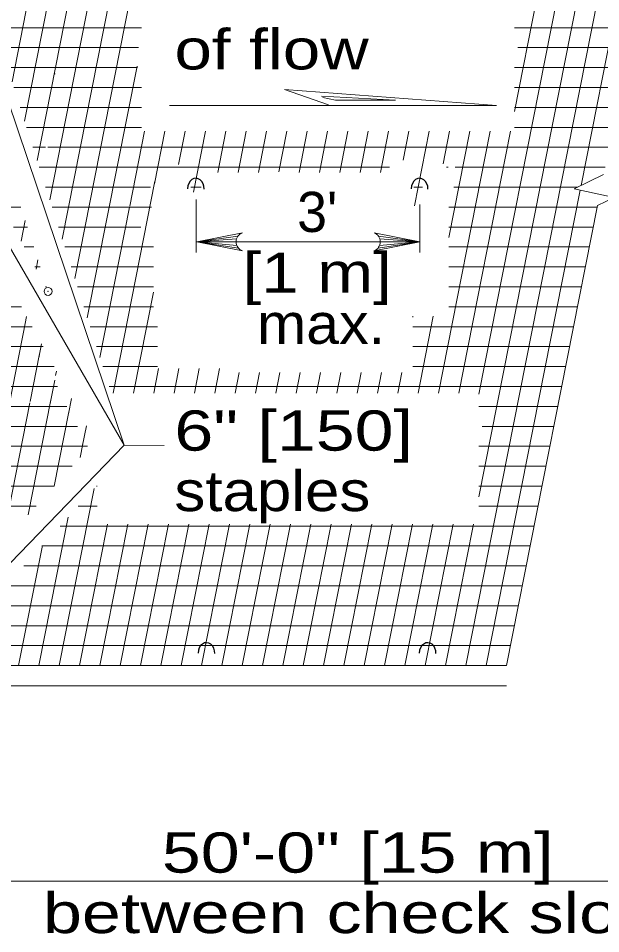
# Model space of a CAD drawing. Extents: x 1083.1 to 1117.1, y 719.4 to 741.4.
# Drawn here: x 1101.052 to 1103.312, y 726.357 to 729.91 of the extents above; entities that cross this region are included whole.
import ezdxf
from ezdxf.enums import TextEntityAlignment as Align

# ---------------------------------------------------------------- set-up
doc = ezdxf.new("R2010")
doc.units = 0
doc.header["$LTSCALE"] = 0.062
doc.header["$PDMODE"] = 32
doc.header["$PDSIZE"] = 0.031
doc.layers.add('1', color=7, linetype='Continuous', lineweight=13)

msp = doc.modelspace()

# ---------------------------------------------------------------- linework, layer by layer
at = {"layer": '1'}
for p, q in [((1101.07625, 729.5115), (1101.36217, 730.95708)), ((1102.78825, 727.39792), (1103.49175, 730.95708)), ((1102.83858, 728.45092), (1103.334, 730.95708)), ((1102.83867, 728.05233), (1103.41283, 730.95708)), ((1102.97675, 729.54875), (1103.25508, 730.95708)), ((1103.23542, 729.26133), (1103.57058, 730.95708)), ((1101.17367, 729.2055), (1101.48558, 730.7835)), ((1101.46192, 728.25383), (1100.61817, 730.75558)), ((1101.22225, 729.05292), (1101.53617, 730.64)), ((1101.12475, 729.35892), (1101.3035, 730.26167)), ((1101.02758, 729.66417), (1101.11492, 730.10608)), ((1101.27092, 728.9), (1101.50892, 730.10408)), ((1101.19833, 729.87383), (1100.96083, 729.87383)), ((1101.52983, 729.87383), (1101.19833, 729.87383)), ((1103.43542, 729.87383), (1102.97675, 729.87383)), ((1101.18775, 729.7965), (1100.9855, 729.7965)), ((1101.51842, 729.7965), (1101.18775, 729.7965)), ((1103.42008, 729.7965), (1102.98983, 729.7965)), ((1101.17717, 729.71908), (1101.01008, 729.71908)), ((1101.51475, 729.71908), (1101.17717, 729.71908)), ((1101.31958, 728.74725), (1101.51275, 729.72433)), ((1103.40483, 729.71908), (1102.97675, 729.71908)), ((1101.19017, 729.695), (1101.195, 729.695)), ((1101.16875, 729.64175), (1101.03475, 729.64175)), ((1101.52983, 729.64175), (1101.16875, 729.64175)), ((1103.3895, 729.64175), (1102.97675, 729.64175)), ((1101.17075, 729.56442), (1101.05942, 729.56442)), ((1101.52983, 729.56442), (1101.17075, 729.56442)), ((1101.63817, 729.57175), (1102.90775, 729.57175)), ((1103.37417, 729.56442), (1102.97675, 729.56442)), ((1101.18008, 729.487), (1101.084, 729.487)), ((1101.52983, 729.487), (1101.18008, 729.487)), ((1103.359, 729.487), (1102.97675, 729.487)), ((1101.48417, 729.18058), (1101.54192, 729.47283)), ((1101.58033, 729.26833), (1101.62075, 729.47283)), ((1101.674, 729.34317), (1101.69967, 729.47283)), ((1101.73183, 729.23608), (1101.77858, 729.47283)), ((1101.8255, 729.3115), (1101.85742, 729.47283)), ((1101.90442, 729.3115), (1101.93633, 729.47283)), ((1101.98325, 729.3115), (1102.01517, 729.47283)), ((1102.06283, 729.31483), (1102.09408, 729.47283)), ((1102.141, 729.3115), (1102.17292, 729.47283)), ((1102.21992, 729.3115), (1102.25183, 729.47283)), ((1102.29883, 729.3115), (1102.33058, 729.47242)), ((1102.37767, 729.3115), (1102.40958, 729.47283)), ((1102.45658, 729.3115), (1102.48842, 729.47283)), ((1102.54483, 729.35925), (1102.56733, 729.47283)), ((1102.58858, 729.18175), (1102.64617, 729.47283)), ((1102.68167, 728.45517), (1102.88283, 729.47283)), ((1102.69983, 729.34525), (1102.72508, 729.47283)), ((1102.72208, 729.05917), (1102.80392, 729.47283)), ((1102.7605, 728.45517), (1102.96175, 729.47283)), ((1101.15683, 729.40967), (1101.10867, 729.40967)), ((1101.16033, 729.33225), (1101.13325, 729.33225)), ((1101.86742, 729.33225), (1101.80475, 729.33225)), ((1102.71367, 729.33225), (1102.72017, 729.33225)), ((1102.74633, 729.33225), (1103.32833, 729.33225)), ((1101.41958, 728.45517), (1101.58217, 729.27775)), ((1103.32267, 729.30358), (1103.20867, 729.24833)), ((1101.1615, 729.25492), (1101.15792, 729.25492)), ((1101.75983, 729.25492), (1101.72083, 729.25492)), ((1101.72083, 729.25492), (1101.76192, 729.25492)), ((1102.586, 729.25492), (1102.62025, 729.25492)), ((1102.74142, 729.25492), (1103.22225, 729.25492)), ((1102.86708, 727.39792), (1103.23183, 729.24325)), ((1101.74133, 729.20692), (1101.74133, 729.00108)), ((1101.062, 729.1775), (1100.99092, 729.1775)), ((1101.36825, 728.59433), (1101.4835, 729.177)), ((1102.60925, 729.18758), (1102.60925, 729.00108)), ((1102.72208, 729.1775), (1103.29775, 729.1775)), ((1102.946, 727.39792), (1103.29883, 729.18333)), ((1101.03267, 729.10017), (1101.08692, 729.10017)), ((1101.06258, 729.04467), (1101.07867, 729.12583)), ((1101.20717, 729.10017), (1101.52725, 729.10017)), ((1102.72208, 729.10017), (1103.2825, 729.10017)), ((1101.90442, 729.06517), (1101.74417, 729.04275)), ((1102.44908, 729.06517), (1102.60933, 729.04275)), ((1102.72208, 729.06808), (1102.72217, 729.0685)), ((1101.74133, 729.04275), (1102.60933, 729.04275)), ((1101.899, 729.05408), (1101.74417, 729.04275)), ((1101.89733, 729.04275), (1101.74417, 729.04275)), ((1101.90017, 729.02833), (1101.74417, 729.04275)), ((1101.90633, 729.018), (1101.74417, 729.04275)), ((1102.44717, 729.018), (1102.60933, 729.04275)), ((1102.45333, 729.02833), (1102.60933, 729.04275)), ((1102.4545, 729.05408), (1102.60933, 729.04275)), ((1102.45617, 729.04275), (1102.60933, 729.04275)), ((1101.07433, 729.02275), (1101.11183, 729.02275)), ((1101.23183, 729.02275), (1101.31108, 729.02275)), ((1101.31175, 729.02275), (1101.57592, 729.02275)), ((1102.72208, 729.02275), (1103.26717, 729.02275)), ((1101.12058, 728.93708), (1101.12775, 728.97333)), ((1101.11608, 728.94542), (1101.13675, 728.94542)), ((1101.2565, 728.94542), (1101.57592, 728.94542)), ((1102.72208, 728.94542), (1103.25183, 728.94542)), ((1101.15783, 728.868), (1101.16167, 728.868)), ((1101.28108, 728.868), (1101.28533, 728.868)), ((1101.28533, 728.868), (1101.57592, 728.868)), ((1102.72208, 728.868), (1103.23658, 728.868)), ((1101.4985, 728.45517), (1101.57592, 728.84675)), ((1100.64575, 728.79067), (1101.05875, 728.79067)), ((1101.0585, 728.79067), (1101.06367, 728.79067)), ((1101.30575, 728.79067), (1101.57592, 728.79067)), ((1102.72208, 728.79067), (1103.22125, 728.79067)), ((1101.07883, 728.72617), (1101.08417, 728.75308)), ((1102.58242, 728.75092), (1102.58308, 728.75425)), ((1102.60275, 728.45517), (1102.66183, 728.75425)), ((1100.6305, 728.71325), (1101.10592, 728.71325)), ((1101.016, 728.4085), (1101.08125, 728.73875)), ((1101.33125, 728.71325), (1101.59175, 728.71325)), ((1102.58242, 728.71325), (1103.206, 728.71325)), ((1100.61517, 728.63592), (1101.14817, 728.63592)), ((1101.13125, 728.593), (1101.142, 728.64717)), ((1101.355, 728.63592), (1101.42058, 728.63592)), ((1101.355, 728.63592), (1101.59175, 728.63592)), ((1102.58242, 728.63592), (1103.19067, 728.63592)), ((1101.09775, 728.42333), (1101.13417, 728.6075)), ((1100.59983, 728.5585), (1101.1565, 728.5585)), ((1101.05475, 728.5585), (1101.19033, 728.5585)), ((1101.19658, 728.52367), (1101.2, 728.54092)), ((1101.37967, 728.5585), (1101.59175, 728.5585)), ((1101.5775, 728.45517), (1101.59633, 728.5505)), ((1101.65625, 728.45517), (1101.67508, 728.5505)), ((1101.73517, 728.45517), (1101.754, 728.5505)), ((1101.814, 728.45517), (1101.83283, 728.5505)), ((1101.89292, 728.45517), (1101.90883, 728.536)), ((1101.97175, 728.45517), (1101.98775, 728.536)), ((1102.05075, 728.45517), (1102.06667, 728.536)), ((1102.1295, 728.45517), (1102.1455, 728.536)), ((1102.20842, 728.45517), (1102.22442, 728.536)), ((1102.28733, 728.45517), (1102.30325, 728.536)), ((1102.36617, 728.45517), (1102.38217, 728.536)), ((1102.445, 728.45517), (1102.46092, 728.536)), ((1102.52392, 728.45517), (1102.53992, 728.536)), ((1102.58242, 728.5585), (1103.17542, 728.5585)), ((1101.17508, 728.41517), (1101.19292, 728.50542)), ((1100.58458, 728.48117), (1101.20433, 728.48117)), ((1101.40425, 728.48117), (1103.16017, 728.48117)), ((1101.08958, 727.98258), (1101.17783, 728.42908)), ((1101.246, 728.37508), (1101.25783, 728.43492)), ((1100.56925, 728.40383), (1101.23992, 728.40383)), ((1100.98858, 727.87075), (1101.09675, 728.41808)), ((1102.83858, 728.40383), (1103.14483, 728.40383)), ((1101.19058, 728.09442), (1101.2475, 728.3825)), ((1100.554, 728.32642), (1101.2815, 728.32642)), ((1101.2995, 728.24658), (1101.31575, 728.32883)), ((1102.85175, 728.32642), (1103.1295, 728.32642)), ((1100.96708, 728.24908), (1101.32, 728.24908)), ((1101.2915, 728.20625), (1101.30175, 728.25808)), ((1101.46192, 728.25383), (1101.61792, 728.25283)), ((1102.83858, 728.24908), (1103.11425, 728.24908)), ((1100.86633, 728.17167), (1101.26033, 728.17167)), ((1102.83867, 728.17167), (1103.09892, 728.17167)), ((1100.82008, 728.09433), (1101.19042, 728.09433)), ((1101.21067, 727.39792), (1101.34642, 728.08508)), ((1101.35483, 728.09433), (1101.35825, 728.09433)), ((1102.83867, 728.09433), (1103.08367, 728.09433)), ((1100.77883, 728.01692), (1101.12058, 728.01692)), ((1101.28425, 728.01692), (1101.35825, 728.01692)), ((1102.83867, 728.01692), (1103.06833, 728.01692)), ((1101.13175, 727.39792), (1101.24575, 727.97467)), ((1101.21375, 727.93958), (1103.053, 727.93958)), ((1101.2895, 727.39792), (1101.39792, 727.9465)), ((1101.36842, 727.39792), (1101.47683, 727.9465)), ((1101.44725, 727.39792), (1101.55575, 727.9465)), ((1101.52617, 727.39792), (1101.63458, 727.9465)), ((1101.605, 727.39792), (1101.7135, 727.9465)), ((1101.68392, 727.39792), (1101.79242, 727.9465)), ((1101.76283, 727.39792), (1101.87125, 727.9465)), ((1101.84167, 727.39792), (1101.95017, 727.9465)), ((1101.92058, 727.39792), (1102.029, 727.9465)), ((1101.99942, 727.39792), (1102.10783, 727.9465)), ((1102.07833, 727.39792), (1102.18675, 727.9465)), ((1102.15717, 727.39792), (1102.26567, 727.9465)), ((1102.23608, 727.39792), (1102.3445, 727.9465)), ((1102.31492, 727.39792), (1102.42342, 727.9465)), ((1102.39383, 727.39792), (1102.50225, 727.9465)), ((1102.47275, 727.39792), (1102.58117, 727.9465)), ((1102.55158, 727.39792), (1102.66, 727.9465)), ((1102.6305, 727.39792), (1102.73892, 727.9465)), ((1102.70933, 727.39792), (1102.81775, 727.9465)), ((1101.05292, 727.39792), (1101.14508, 727.86417)), ((1101.14325, 727.86217), (1103.03775, 727.86217)), ((1101.07275, 727.78483), (1103.02242, 727.78483)), ((1101.00225, 727.70742), (1103.00717, 727.70742)), ((1100.93167, 727.63008), (1102.99192, 727.63008)), ((1100.86117, 727.55267), (1102.97658, 727.55267)), ((1100.79067, 727.47533), (1102.96133, 727.47533)), ((1100.37042, 727.39792), (1102.946, 727.39792)), ((1100.37042, 727.31908), (1102.946, 727.31908)), ((1100.37042, 726.56167), (1101.59783, 726.56167)), ((1101.59783, 726.56167), (1103.66917, 726.56167))]:
    msp.add_line(p, q, dxfattribs=at)
for points in [[(1102.90775, 729.57175), (1102.08442, 729.63442), (1102.25567, 729.57433)], [(1102.22825, 729.60825), (1102.51592, 729.59258), (1102.28275, 729.59258), (1102.23325, 729.603)], [(1101.88275, 729.40967), (1101.1665, 729.40967), (1103.34367, 729.40967)], [(1101.63358, 729.33225), (1101.16033, 729.33225), (1102.49167, 729.33225)], [(1101.56483, 729.25492), (1101.1615, 729.25492), (1101.56483, 729.25492)], [(1103.20867, 729.24833), (1103.36333, 729.21458), (1103.29892, 729.18333)], [(1100.89425, 729.23417), (1101.46192, 728.25383), (1100.72508, 727.49092)], [(1101.56883, 729.1775), (1101.18258, 729.1775), (1101.481, 729.1775)], [(1101.92117, 729.00733), (1101.74417, 729.04275), (1101.92117, 729.07817)], [(1102.43233, 729.00733), (1102.60933, 729.04275), (1102.43233, 729.07817)]]:
    msp.add_lwpolyline(points, dxfattribs=at)
for centre, start, end in [((1101.93548, 729.0428), 112.08782, 247.91395), ((1102.41802, 729.0428), 292.08605, 67.91218)]:
    msp.add_arc(centre, 0.0382, start, end, dxfattribs=at)
at = {"layer": '1', "lineweight": 25}
for centre in [(1101.74078, 729.24819), (1102.60879, 729.24819), (1101.78151, 727.4459), (1102.64003, 727.4459)]:
    msp.add_ellipse(centre, major_axis=(0.00099, 0.04097), ratio=0.78812, start_param=4.7123995, end_param=7.8539922, dxfattribs=at)
at = {"layer": '1'}
msp.add_point((1101.16742, 728.85017), dxfattribs=at)

# ---------------------------------------------------------------- texts
for s, width, p in [('of flow', 1.25, (1101.65783, 729.71183)), ('6" [150]', 1.3, (1101.6575, 728.23225)), ('staples', 1.15, (1101.6575, 727.99758))]:
    msp.add_text(s, height=0.156, dxfattribs=dict(at, width=width)).set_placement(p)
msp.add_text("3'", height=0.156, dxfattribs=at).set_placement((1102.2115, 729.08092), align=Align.CENTER)
for s, width, p in [('[1 m]', 1.25, (1102.21146, 728.84492)), ('max.', 1.1, (1102.22642, 728.64667)), ('50\'-0" [15 m]', 1.3, (1102.36879, 726.59433)), ('between check slots', 1.3, (1102.36879, 726.35967))]:
    msp.add_text(s, height=0.156, dxfattribs=dict(at, width=width)).set_placement(p, align=Align.CENTER)

doc.saveas('drawing.dxf')
